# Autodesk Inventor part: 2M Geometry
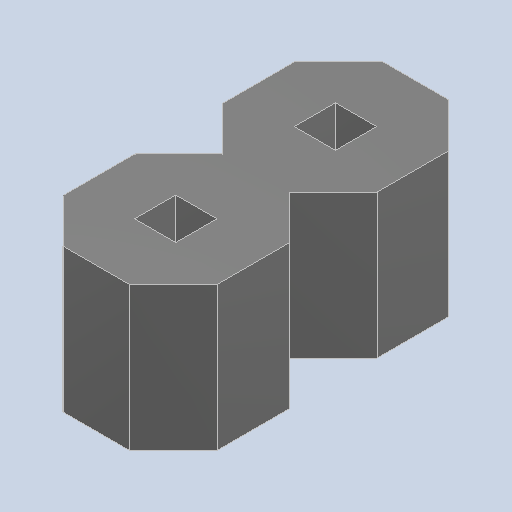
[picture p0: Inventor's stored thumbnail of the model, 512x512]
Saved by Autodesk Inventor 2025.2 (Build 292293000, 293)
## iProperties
Created: 2025-04
Part Number: 2M Geometry
Material: Generic
Description: PART-2M Geometry-DESC
Document SubType Name: Modeling
Designer: BennF
Density: 1 g/cm^3
Appearance: Default
Author: BennF
Revision Number: NONE
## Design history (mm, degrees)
feature "4"
body "Solid1"
